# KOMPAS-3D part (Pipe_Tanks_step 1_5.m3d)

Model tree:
1. X Axis
2. Y Axis
3. Z Axis  (labels: Bend 90 Dn 50; Pipe Dn 50; T-Bend Dn 50; C:\Program Files\ASCON\KOMPAS-3D V10\Sys\graphic.lyt)
     Òîëùèíà ñòåíêè 1 = 1

Referenced files in C:\Documents and Settings\kashirsky\Мои документы\Camtasia Studio\Pipelines3D\Tanks\: Tanks_step 1.a3d, Tanks_step 1.spw
Referenced files in C:\Documents and Settings\kashirsky\Мои документы\Camtasia Studio\Pipelines3D\Tanks\Tanks_step 1_Pipes\: Pipe_Tanks_step 1_5.m3d
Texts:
  Pipe Dn 50
  Steel ASTM A295
  Three Point Plane
  Plane at Angle
  Line and Point Plane
  Axis through Two Vertices
  Axis of Feature
  Axis of Conical Surface
  Axis through Edge
  Trim by Surface
  Trim by Sketch
  Feature with No History
  Intersection Axis of Two Planes
  Two Line Plane
  Line and Face Plane
  Bend by line
  Hole in sheet body
  Cut in sheet body
  Point in CM
  Linear Dimension from Line to Point
  Surface Finish Symbol
  Geometric Tolerance Symbol
  Leader #1
  Leader #2
  Leader #3
  Shape Deviations and Datum
  Node point number
  Mark of coordination axis
  Node point designation
  Mark/Reference designation with leader
  Mark/reference designation on line
  Mark/Reference designation without leader
  Bend 90 Dn 50
  T-Bend Dn 50
  Plane of section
